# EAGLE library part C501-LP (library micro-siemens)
MICROPROCESSOR/PERIPHERAL DEVICE
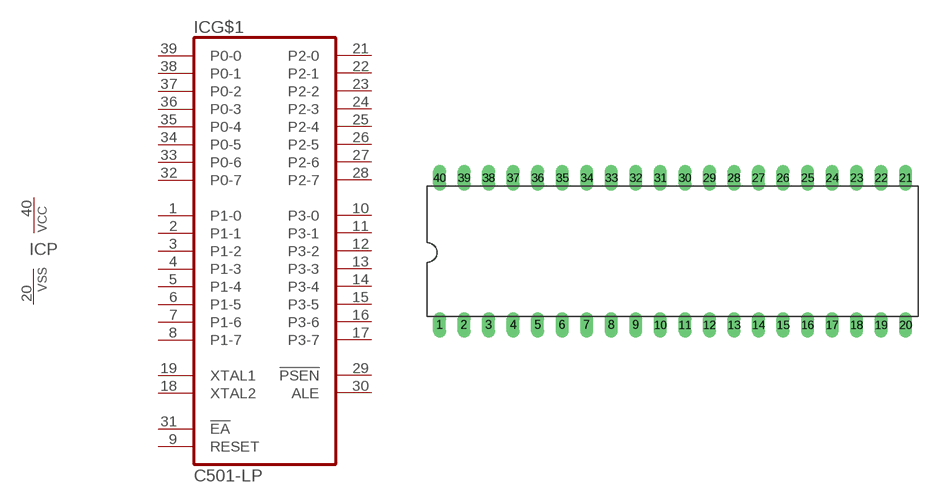
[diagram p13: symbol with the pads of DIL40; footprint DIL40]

Designator prefix IC; gates G$1=C501-LP P=VCCVSS

## C501-LP (OC_FARNELL: unknown; OC_NEWARK: unknown)  [DIL40]
1  G$1:P1-0
2  G$1:P1-1
3  G$1:P1-2
4  G$1:P1-3
5  G$1:P1-4
6  G$1:P1-5
7  G$1:P1-6
8  G$1:P1-7
9  G$1:RESET  in
10  G$1:P3-0
11  G$1:P3-1
12  G$1:P3-2
13  G$1:P3-3
14  G$1:P3-4
15  G$1:P3-5
16  G$1:P3-6
17  G$1:P3-7
18  G$1:XTAL2  pas
19  G$1:XTAL1  pas
20  P:VSS  pwr
21  G$1:P2-0
22  G$1:P2-1
23  G$1:P2-2
24  G$1:P2-3
25  G$1:P2-4
26  G$1:P2-5
27  G$1:P2-6
28  G$1:P2-7
29  G$1:!PSEN  out
30  G$1:ALE  out
31  G$1:!EA  in
32  G$1:P0-7
33  G$1:P0-6
34  G$1:P0-5
35  G$1:P0-4
36  G$1:P0-3
37  G$1:P0-2
38  G$1:P0-1
39  G$1:P0-0
40  P:VCC  pwr

## Footprint DIL40 (pad centres in mm)
Dual In Line Package
drill 0.813 long: 1 -24.13,-7.62; 2 -21.59,-7.62; 3 -19.05,-7.62; 4 -16.51,-7.62; 5 -13.97,-7.62; 6 -11.43,-7.62; 7 -8.89,-7.62; 8 -6.35,-7.62; 9 -3.81,-7.62; 10 -1.27,-7.62; 11 1.27,-7.62; 12 3.81,-7.62; 13 6.35,-7.62; 14 8.89,-7.62; 15 11.43,-7.62; 16 13.97,-7.62; 17 16.51,-7.62; 18 19.05,-7.62; 19 21.59,-7.62; 20 24.13,-7.62; 21 24.13,7.62; 22 21.59,7.62; 23 19.05,7.62; 24 16.51,7.62; 25 13.97,7.62; 26 11.43,7.62; 27 8.89,7.62; 28 6.35,7.62; 29 3.81,7.62; 30 1.27,7.62; 31 -1.27,7.62; 32 -3.81,7.62; 33 -6.35,7.62; 34 -8.89,7.62; 35 -11.43,7.62; 36 -13.97,7.62; 37 -16.51,7.62; 38 -19.05,7.62; 39 -21.59,7.62; 40 -24.13,7.62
